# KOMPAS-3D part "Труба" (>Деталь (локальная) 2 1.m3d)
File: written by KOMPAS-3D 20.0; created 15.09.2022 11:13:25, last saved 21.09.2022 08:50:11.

Document properties: Полное имя файла: C:\Users\yakovlev_sv\AppData\Local\Temp\KOMPAS-3D\ktfc-c50a-a903-a35f\_Деталь (локальная) 2 1.m3d

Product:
- Part/product: Труба
    Материал: Сталь 45  ГОСТ 1050-2013 (density 7810 kg/m3)
    Масса: 15932.7

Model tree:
1. Плоскость под углом:1
     Угол = 30
2. Эскиз:1
3. Обечайка:1
     Расстояние 1 = 2500; Толщина листового тела = 150; Радиус сгиба = 850; Коэффициент = 0.4; Величина сгиба = 10; Зазор = 0.01
4. Эскиз:2  (with: Обечайка:1)
5. Вырез в листовом теле:2
     Глубина выреза = 2220
6. Касательная плоскость:1  (with: Обечайка:1)
7. Развертка  (labels: Сталь 45  ГОСТ 1050-2013)

Expressions: v83*2
Referenced files in D:\YAKOVLEV\ПРОЕКТЫ\ДЦ-2. ДП-7 Газопровод Окожушивание\ПРОБА Соединение труб. Окожушивание\ПРОБА 2\: Соединение труб -2.a3d
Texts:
  Соединение труб. Окожушивание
